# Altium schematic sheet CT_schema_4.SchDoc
size 368 x 245 mm
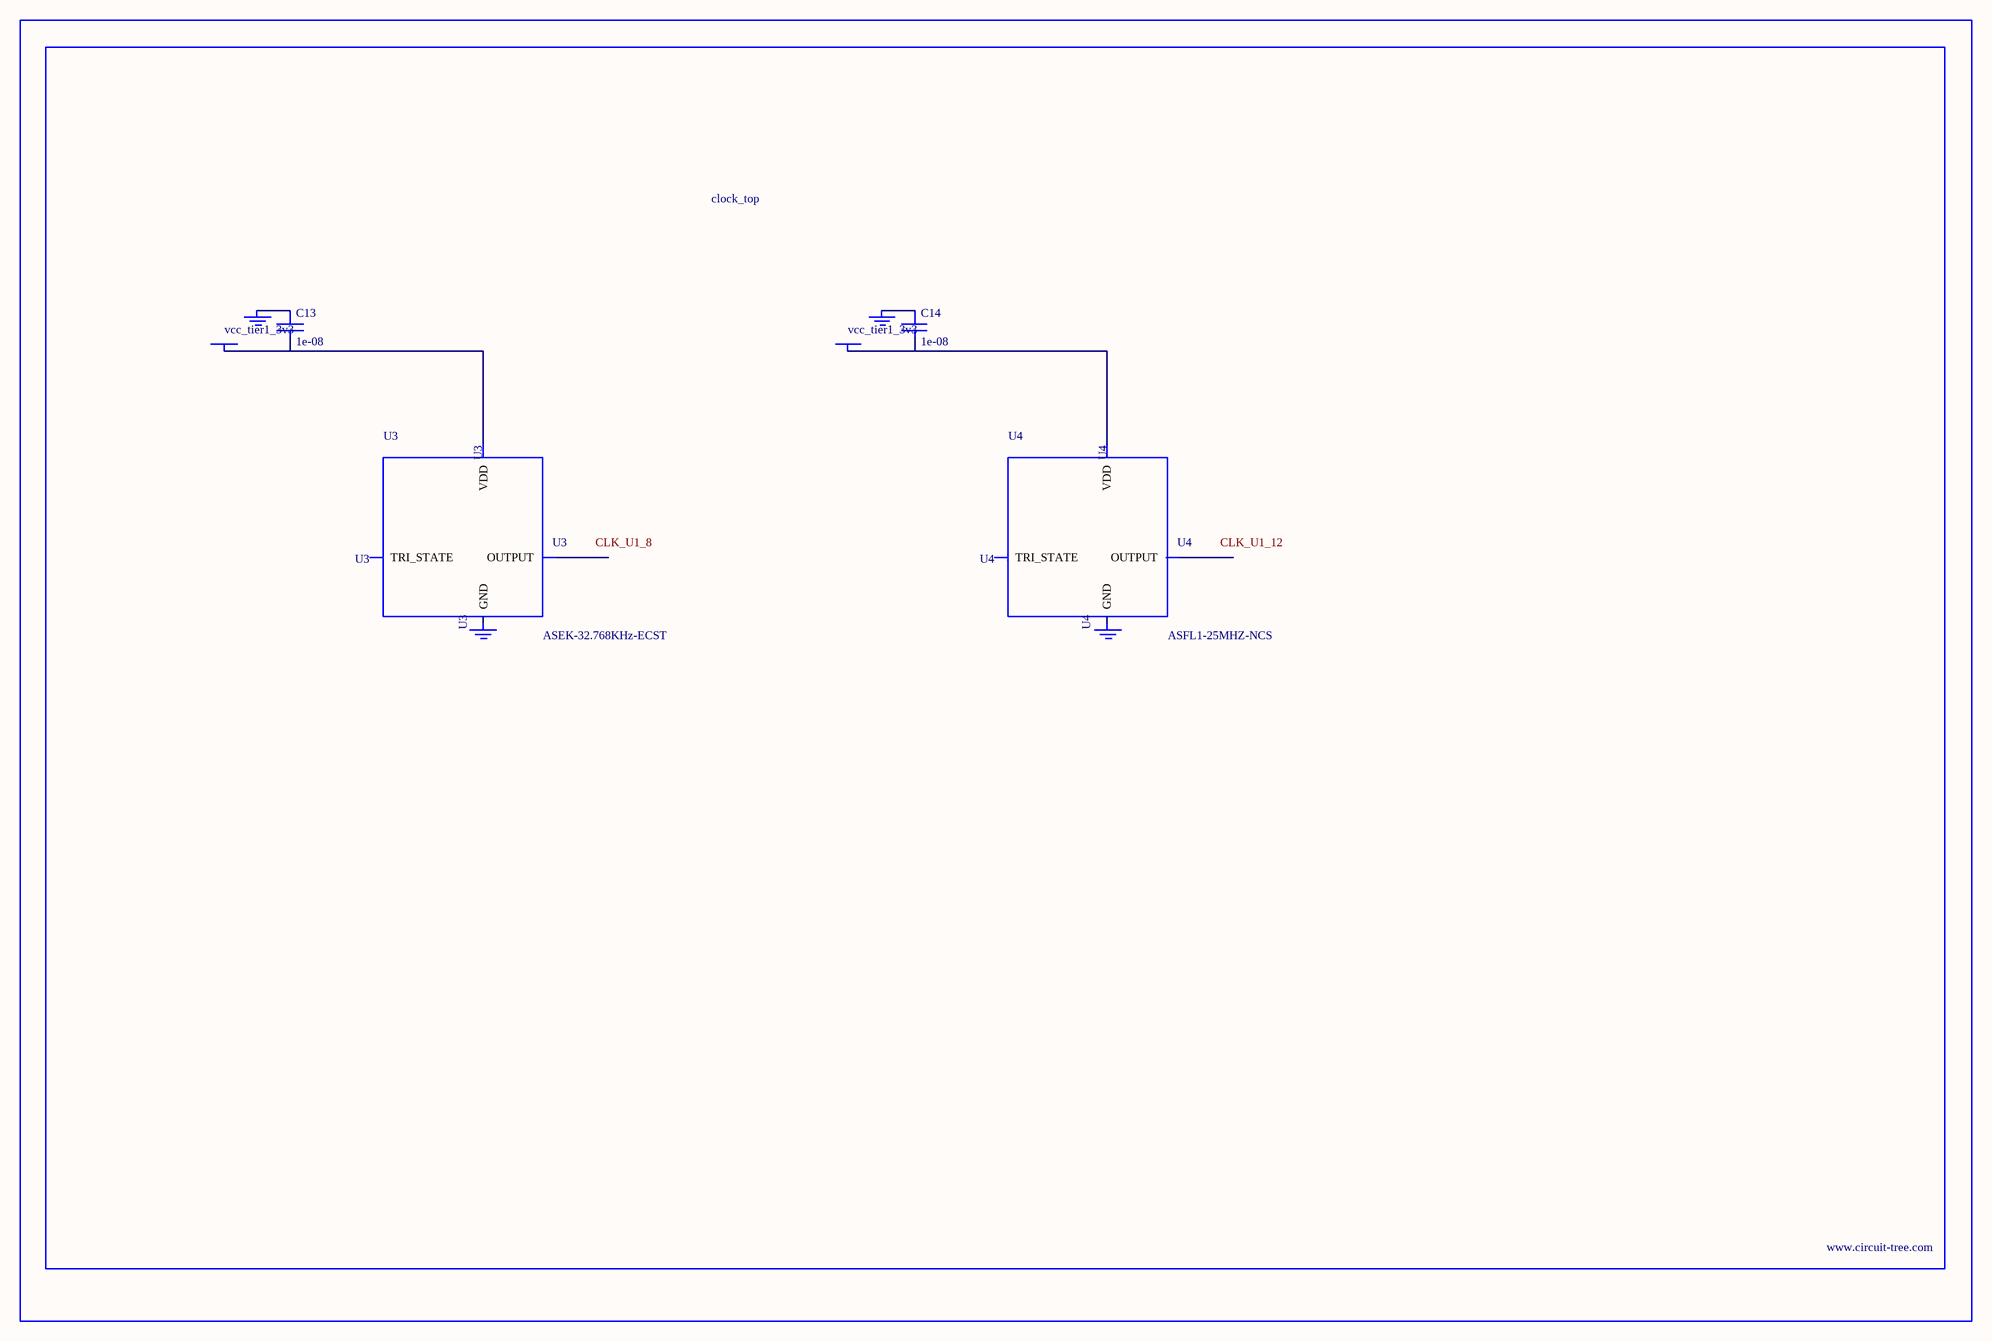
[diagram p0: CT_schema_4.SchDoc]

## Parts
BORDER3  (no value)
C13  1e-08  [C0402]
C14  1e-08  [C0402]
GND_INSTANCE_3_0  (no value)
GND_INSTANCE_3_1  (no value)
GND_INSTANCE_3_2  (no value)
GND_INSTANCE_3_3  (no value)
POWER_INSTANCE_3_0  vcc_tier1_3v3
POWER_INSTANCE_3_1  vcc_tier1_3v3
U3  ASEK-32.768KHz-ECST  [ASEK]
U4  ASFL1-25MHZ-NCS  [ASFL1]

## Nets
NetC13_1: C13.1 GND_INSTANCE_3_0.0(GND)
NetC13_2: C13.2 POWER_INSTANCE_3_0.0(PWR) U3.4(VDD)
NetC14_1: C14.1 GND_INSTANCE_3_2.0(GND)
NetC14_2: C14.2 POWER_INSTANCE_3_1.0(PWR) U4.4(VDD)

Not connected (* = marked no-connect by the designer): GND_INSTANCE_3_1 0(GND); GND_INSTANCE_3_3 0(GND); U3 1(TRI_STATE) 2(GND) 3(OUTPUT); U4 1(TRI_STATE) 2(GND) 3(OUTPUT)

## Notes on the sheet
- Labels drawn without touching a wire or pin: CLK_U1_8, CLK_U1_12

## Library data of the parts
BORDER3 = BORDER_PAGE3
C13 C14 = C0402C103K3RAC
GND_INSTANCE_3_0-GND_INSTANCE_3_3 = GND
POWER_INSTANCE_3_0 POWER_INSTANCE_3_1 = PWR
